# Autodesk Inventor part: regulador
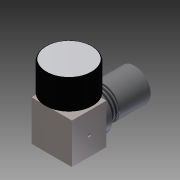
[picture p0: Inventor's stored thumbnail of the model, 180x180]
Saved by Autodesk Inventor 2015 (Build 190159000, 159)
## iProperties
Created: 2016-06
Part Number: regulador
Material: Genérico
Document SubType Name: Modeling
Designer: Diego
Density: 1 g/cm^3
Appearance: Valor por defecto
Author: Diego
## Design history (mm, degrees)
sketch "Boceto1"
  geometry: L1 (0, 0)-(35, 0); L2 (35, 0)-(35, 30); L3 (35, 30)-(0, 30); L4 (0, 30)-(0, 0)
  constraints: 8 end point, 2 parallel, 1 horizontal, 1 perpendicular
  dimensions: "d0" = 35 distance of L3.end L2.end; "d1" = 30 distance of L2.end L1.end
extrude "Extrusión1" new body sketch "Boceto1" distance "d2" = 35; taper "d3" = 0 deg
sketch "Boceto2"
  geometry: C1 r 17.534 at (17.5, -17.5); 1 further point
  constraints: 1 centre point
extrude "Extrusión2" join sketch "Boceto2" distance "d4" = 5; taper "d5" = 0 deg
sketch "Boceto3" dims "d31" = 3
  geometry: C1 r 13.5 at (0, 0); 1 further point
  constraints: 1 centre point
  dimensions: "d6" = 27 diameter of C1
extrude "Extrusión3" join sketch "Boceto3" distance "d7" = 10; taper "d8" = 0 deg
feature "Rosca1" dims "d9" = 10, "d10" = 0
sketch "Boceto4"
  geometry: C1 r 14 at (0, 0); 1 further point
  constraints: 1 centre point
  dimensions: "d11" = 28 diameter of C1
extrude "Extrusión4" join sketch "Boceto4" distance "d12" = 27; taper "d13" = 0 deg
sketch "Boceto5"
  geometry: C1 r 5 at (17.5, 15); 1 further point
  constraints: 1 centre point
  dimensions: "d14" = 10 diameter of C1
extrude "Extrusión5" join sketch "Boceto5" distance "d15" = 5; taper "d16" = 0 deg
sketch "Boceto6"
  geometry: C1 r 20.5 at (0, 0); 1 further point
  constraints: 1 centre point
  dimensions: "d17" = 41 diameter of C1
extrude "Extrusión6" join sketch "Boceto6" distance "d18" = 25; taper "d19" = 0 deg
sketch "Boceto7"
  geometry: C1 r 20.5 at (0, 0) reference; C2 r 19.5 at (0, 0); 1 further point
  constraints: 1 centre point
  dimensions: "d20" = 1 radial gap between concentric circles of C1 C2
extrude "Extrusión7" join sketch "Boceto7" distance "d21" = 2; taper "d22" = 0 deg
fillet "Empalme1" dims "d23" = 2
sketch "Boceto8"
  geometry: 2 further points
hole "Agujero1" sketch "Boceto8" at (16.415, 15) diameter "d24" = 3; stored, may be unused: countersink angle "d28" = 90 deg, drill point angle "d30" = 118 deg; dims "d25" = 6, "d26" = 4, "d27" = 2, "d29" = 1
sketch "Boceto9"
  geometry: 2 further points
hole "Agujero2" sketch "Boceto9" at (-16.415, 15) diameter "d31" = 3; stored, may be unused: countersink angle "d35" = 90 deg, drill point angle "d37" = 118 deg; dims "d32" = 6, "d33" = 4, "d34" = 2, "d36" = 1
node "Sólido1"
